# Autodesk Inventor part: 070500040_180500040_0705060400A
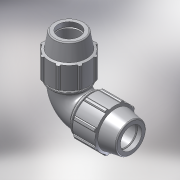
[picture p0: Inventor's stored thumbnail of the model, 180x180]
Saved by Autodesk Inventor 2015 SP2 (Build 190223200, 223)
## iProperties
Created: 2017-02
Part Number: 070500040_180500040_0705060400A
Material: PVC-Piping
Description: PLASSON 90° ELBOW 40-40
Document SubType Name: Modeling
Designer: KIM
Mass: 92.6774 g
Surface Area: 199.44 cm^2
Volume: 66.1981 cm^3
Density: 1.4 g/cm^3
Appearance: Smooth - White
Author: KIM
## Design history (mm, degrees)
derived "07050.ipt"
feature "Solid1::07050.ipt"
tag "TaggingFeature1"
body "Solid1"
other parameters: "d4" = 9, "d5" = 27, "d7" = 82, "d9" = 15.42857, "d11" = 3.6, "d13" = 120 deg, "d15" = 12 deg, "d16" = 71.34, "d18" = 2, "d19" = 35 deg, "d20" = 17.5 deg, "d21" = 76.26, "d23" = 0, "d25" = 360 deg, "d27" = 1.64, "d33" = 0.8, "d42" = 39.96, "d43" = 2.46, "d46" = 1.2, "d51" = 108, "d59" = 90 deg, "d63" = 82, "d64" = 36, "d67" = 61.5, "d68" = 1.8, "d70" = 90 deg, "d71" = 2, "E_" = 82, "A_" = 108, "l_" = 82
